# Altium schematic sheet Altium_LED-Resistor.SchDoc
size A4; SheetNumber: 1; SheetTotal: 1
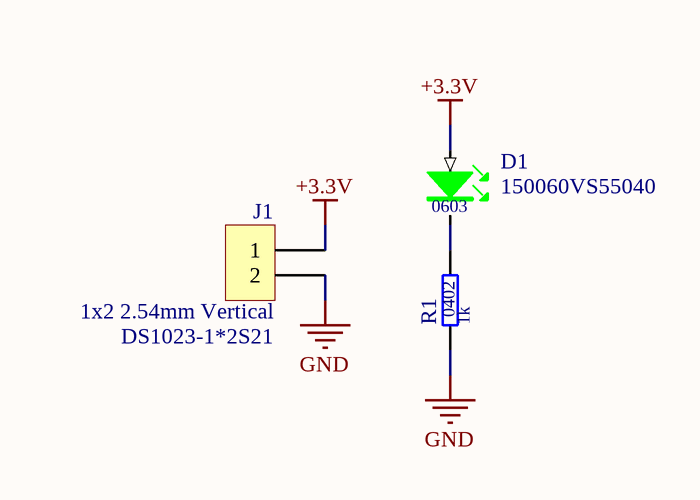
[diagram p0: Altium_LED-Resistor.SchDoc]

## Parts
D1  value 150060VS55040  SCH_Footprint: 0603  [OL_0603_1608]  (hidden comment: Green LED 0603)
J1  value DS1023-1*2S21  SCH_Footprint: 1x2 2.54mm Vertical  [J_HEADER_1x2_2.54_VERTICAL]  (hidden comment: Goldpin female straight)
R1  value 1k  SCH_Footprint: 0402  [R_0402_1005]  (hidden comment: Resistor)

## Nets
+3.3V: D1.2(A) J1.1
GND: J1.2 R1.1
NetD1_1: D1.1(K) R1.2

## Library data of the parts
D1 = OL_G_0603_150060VS55040: LED GREEN; Manufacturer: Wurth
J1 = J_HEADER_1x2_2.54_VERTICAL: Pin Header; Manufacturer: Connfly
R1 = R_1k_0402_1: Manufacturer: Yageo; Manufacturer Part Number: RC0402FR-071K; Voltage: 50V; Power: 63mW; Tolerance: 1%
